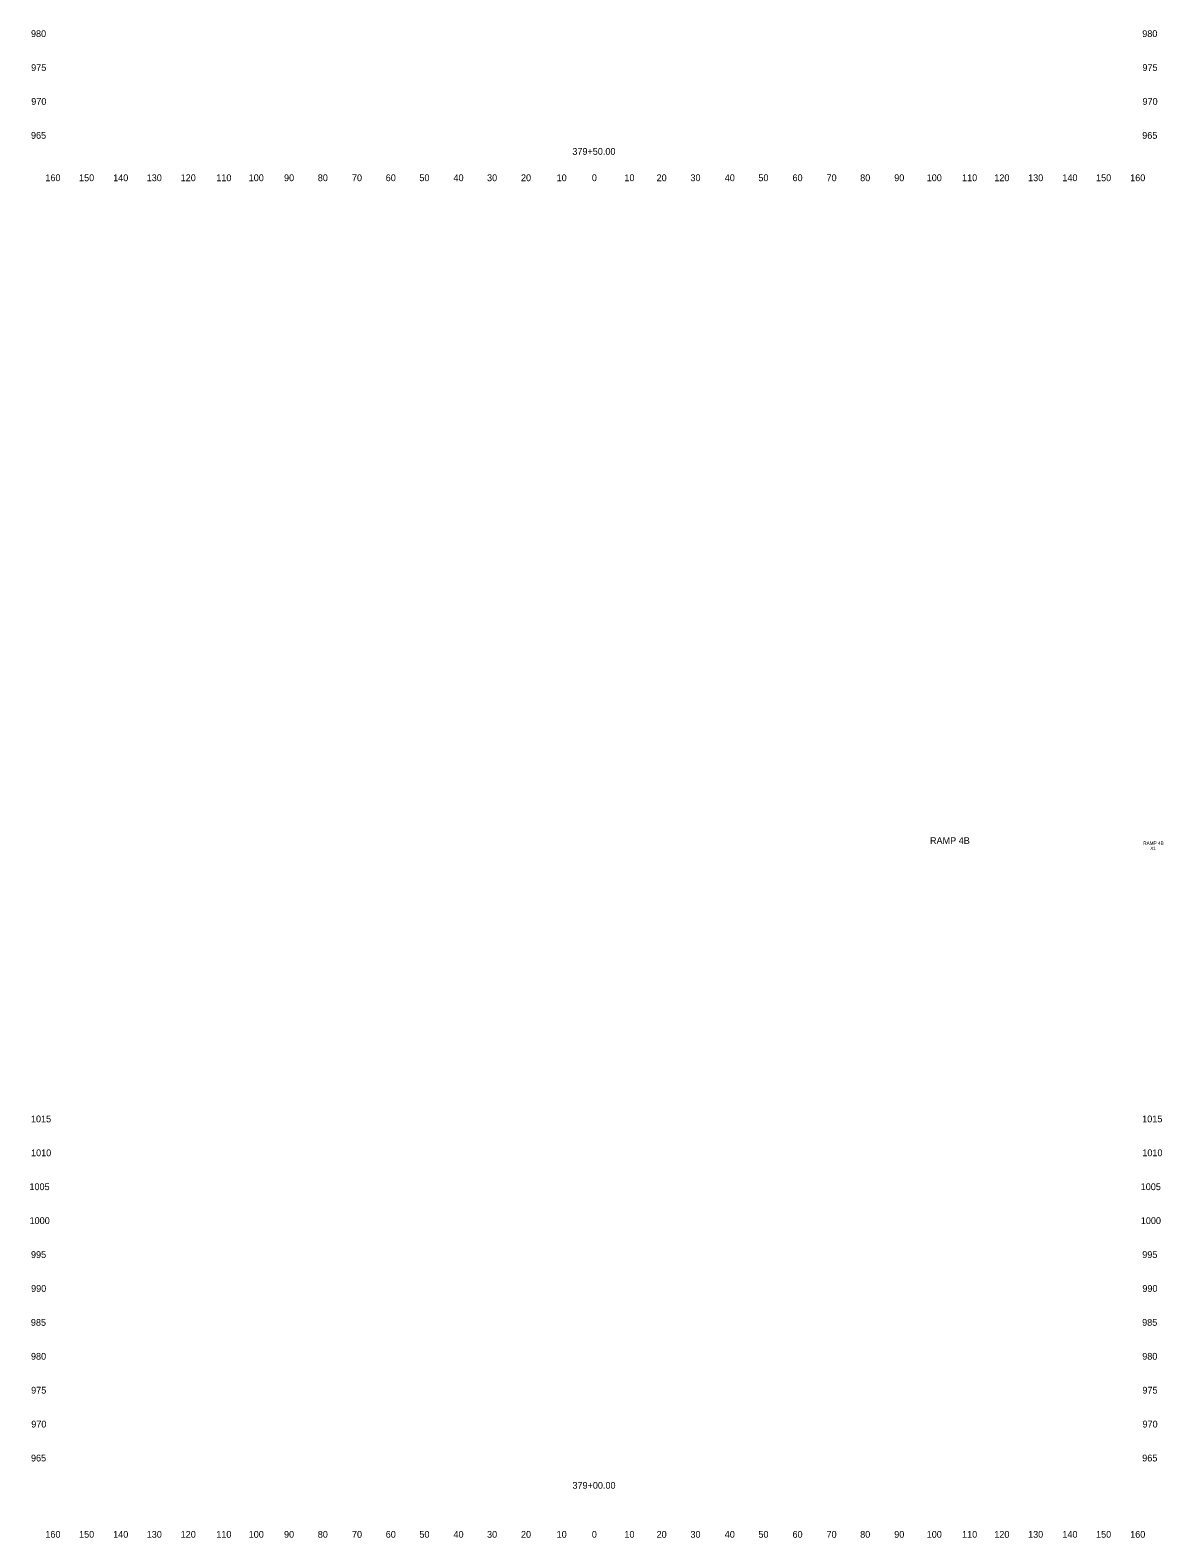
# Model space of a CAD drawing. Extents: x 4994 to 6358, y 4997 to 8804.
# Drawn here: x 4993.6 to 5327.7, y 4997.5 to 5442 of the extents above; entities that cross this region are included whole.
import ezdxf

# ---------------------------------------------------------------- set-up
doc = ezdxf.new("R2010")
doc.units = 0
for name, color, linetype in [('CLS_Search_Dist', 7, 'Continuous'), ('RD_XE_Ground', 7, 'Continuous'), ('UC_PD_Text', 7, 'Continuous')]:
    doc.layers.add(name, color=color, linetype=linetype)

msp = doc.modelspace()

# ---------------------------------------------------------------- texts
at = {"layer": 'CLS_Search_Dist'}
for s, p in [('980', (4993.86, 5440)), ('980', (5321.66, 5440)), ('975', (4993.91, 5430)), ('975', (5321.71, 5430)), ('970', (4993.94, 5420)), ('970', (5321.74, 5420)), ('965', (4993.86, 5410)), ('965', (5321.66, 5410)), ('160', (4998.1, 5397.5)), ('150', (5008.04, 5397.5)), ('140', (5018.1, 5397.5)), ('130', (5027.99, 5397.5)), ('120', (5038.01, 5397.5)), ('110', (5048.51, 5397.5)), ('100', (5058.07, 5397.5)), ('90', (5068.5, 5397.5)), ('80', (5078.46, 5397.5)), ('70', (5088.54, 5397.5)), ('60', (5098.5, 5397.5)), ('50', (5108.43, 5397.5)), ('40', (5118.5, 5397.5)), ('30', (5128.39, 5397.5)), ('20', (5138.4, 5397.5)), ('10', (5148.91, 5397.5)), ('0', (5159.3, 5397.5)), ('0', (5159.3, 5397.5)), ('10', (5168.91, 5397.5)), ('20', (5178.4, 5397.5)), ('30', (5188.39, 5397.5)), ('40', (5198.5, 5397.5)), ('50', (5208.43, 5397.5)), ('60', (5218.5, 5397.5)), ('70', (5228.54, 5397.5)), ('80', (5238.46, 5397.5)), ('90', (5248.5, 5397.5)), ('100', (5258.07, 5397.5)), ('110', (5268.51, 5397.5)), ('120', (5278.01, 5397.5)), ('130', (5287.99, 5397.5)), ('140', (5298.1, 5397.5)), ('150', (5308.04, 5397.5)), ('160', (5318.1, 5397.5)), ('1015', (4993.85, 5120)), ('1015', (5321.65, 5120)), ('1010', (4993.88, 5110)), ('1010', (5321.68, 5110)), ('1005', (4993.4, 5100)), ('1005', (5321.2, 5100)), ('1000', (4993.44, 5090)), ('1000', (5321.24, 5090)), ('995', (4993.86, 5080)), ('995', (5321.66, 5080)), ('990', (4993.89, 5070)), ('990', (5321.69, 5070)), ('985', (4993.83, 5060)), ('985', (5321.63, 5060)), ('980', (4993.86, 5050)), ('980', (5321.66, 5050)), ('975', (4993.91, 5040)), ('975', (5321.71, 5040)), ('970', (4993.94, 5030)), ('970', (5321.74, 5030)), ('965', (4993.86, 5020)), ('965', (5321.66, 5020)), ('160', (4998.1, 4997.5)), ('150', (5008.04, 4997.5)), ('140', (5018.1, 4997.5)), ('130', (5027.99, 4997.5)), ('120', (5038.01, 4997.5)), ('110', (5048.51, 4997.5)), ('100', (5058.07, 4997.5)), ('90', (5068.5, 4997.5)), ('80', (5078.46, 4997.5)), ('70', (5088.54, 4997.5)), ('60', (5098.5, 4997.5)), ('50', (5108.43, 4997.5)), ('40', (5118.5, 4997.5)), ('30', (5128.39, 4997.5)), ('20', (5138.4, 4997.5)), ('10', (5148.91, 4997.5)), ('0', (5159.3, 4997.5)), ('0', (5159.3, 4997.5)), ('10', (5168.91, 4997.5)), ('20', (5178.4, 4997.5)), ('30', (5188.39, 4997.5)), ('40', (5198.5, 4997.5)), ('50', (5208.43, 4997.5)), ('60', (5218.5, 4997.5)), ('70', (5228.54, 4997.5)), ('80', (5238.46, 4997.5)), ('90', (5248.5, 4997.5)), ('100', (5258.07, 4997.5)), ('110', (5268.51, 4997.5)), ('120', (5278.01, 4997.5)), ('130', (5287.99, 4997.5)), ('140', (5298.1, 4997.5)), ('150', (5308.04, 4997.5)), ('160', (5318.1, 4997.5))]:
    msp.add_text(s, height=2, dxfattribs=at).set_placement(p)
at = {"layer": 'RD_XE_Ground'}
for s, p in [('379+50.00', (5153.55, 5405.27)), ('379+00.00', (5153.58, 5011.95))]:
    msp.add_text(s, height=2, dxfattribs=at).set_placement(p)
at = {"layer": 'UC_PD_Text'}
for s, height, p in [('RAMP 4B', 2, (5259.05, 5202.06)), ('RAMP 4B', 1, (5321.94, 5201.8)), ('X1', 1, (5324.02, 5200.3))]:
    msp.add_text(s, height=height, dxfattribs=at).set_placement(p)

doc.saveas('drawing.dxf')
